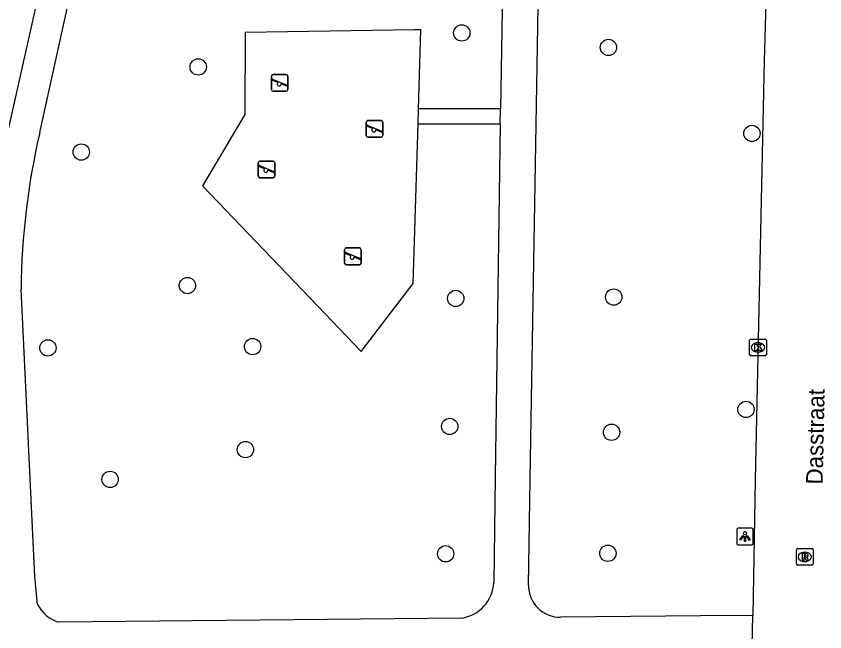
# Model space of a CAD drawing. Extents: x 160026 to 161302, y 384757 to 385701.
# Drawn here: x 160572.18 to 160620.67, y 385069.55 to 385106.46 of the extents above; entities that cross this region are included whole.
import ezdxf

# ---------------------------------------------------------------- set-up
doc = ezdxf.new("R2010")
doc.units = 0
for name, color, linetype in [('IMGEO_Boom', 7, 'Continuous'), ('IMGEO_Groenvoorziening', 7, 'Continuous'), ('IMGEO_Kolk', 7, 'Continuous'), ('IMGEO_Lichtpunt', 7, 'Continuous'), ('IMGEO_Openbare_ruimte_label', 7, 'Continuous'), ('IMGEO_Rijbaan_lokaal_open', 7, 'Continuous'), ('IMGEO_Rioolput', 7, 'Continuous'), ('IMGEO_Speelvoorziening', 7, 'Continuous'), ('IMGEO_Voetpad_halfverhard', 7, 'Continuous'), ('IMGEO_Voetpad_open', 7, 'Continuous')]:
    doc.layers.add(name, color=color, linetype=linetype)

msp = doc.modelspace()

# ---------------------------------------------------------------- linework, layer by layer
at = {"layer": 'IMGEO_Boom'}
for centre in [(160598.907, 385105.453), (160607.7, 385104.584), (160583.098, 385103.416), (160616.302, 385099.428), (160576.086, 385098.313), (160582.456, 385090.311), (160598.543, 385089.536), (160608.015, 385089.62), (160586.361, 385086.65), (160574.086, 385086.576), (160615.942, 385082.883), (160598.183, 385081.863), (160607.884, 385081.515), (160585.934, 385080.475), (160577.817, 385078.689), (160597.938, 385074.229), (160607.664, 385074.262)]:
    msp.add_circle(centre, 0.489, dxfattribs=at)
at = {"layer": 'IMGEO_Groenvoorziening'}
msp.add_lwpolyline([(160596.316, 385100.901), (160596.459, 385105.638), (160596.079, 385105.632), (160585.921, 385105.485), (160585.887, 385100.571), (160583.363, 385096.295), (160590.273, 385089.07), (160592.87, 385086.354), (160595.998, 385090.43), (160596.289, 385100.012)], dxfattribs=at)
at = {"layer": 'IMGEO_Kolk'}
for p, q in [((160616.241, 385087.103), (160617.093, 385087.103)), ((160616.166, 385086.177), (160616.166, 385087.029)), ((160616.654, 385086.883), (160616.679, 385086.883)), ((160617.167, 385087.029), (160617.167, 385086.177)), ((160616.677, 385086.323), (160616.652, 385086.323)), ((160617.093, 385086.103), (160616.241, 385086.103))]:
    msp.add_line(p, q, dxfattribs=at)
for points in [[(160616.241, 385087.103), (160617.093, 385087.103)], [(160616.166, 385086.177), (160616.166, 385087.029)], [(160616.487, 385086.803), (160616.61, 385086.803), (160616.61, 385086.652), (160616.74, 385086.803), (160616.904, 385086.803), (160616.758, 385086.652), (160616.911, 385086.403), (160616.759, 385086.403), (160616.674, 385086.567), (160616.61, 385086.5), (160616.61, 385086.403), (160616.487, 385086.403), (160616.487, 385086.803)], [(160617.167, 385087.029), (160617.167, 385086.177)], [(160617.093, 385086.103), (160616.241, 385086.103)]]:
    msp.add_lwpolyline(points, dxfattribs=at)
for centre, start, end in [((160616.243, 385087.027), 91.552, 178.448), ((160616.243, 385087.027), 91.552, 178.448), ((160617.091, 385087.027), 1.552, 88.448), ((160617.091, 385087.027), 1.552, 88.448), ((160616.243, 385086.179), 181.552, 268.448), ((160616.243, 385086.179), 181.552, 268.448), ((160617.091, 385086.179), 271.552, 358.448), ((160617.091, 385086.179), 271.552, 358.448)]:
    msp.add_arc(centre, 0.0765, start, end, dxfattribs=at)
for centre, major_axis, ratio, start_param, end_param in [((160616.653, 385086.603), (-0.387, 0.002), 0.722429, 4.712389, 7.853982), ((160616.678, 385086.603), (-0.39, 0.002), 0.717154, 1.570796, 4.712389)]:
    msp.add_ellipse(centre, major_axis=major_axis, ratio=ratio, start_param=start_param, end_param=end_param, dxfattribs=at)
at = {"layer": 'IMGEO_Lichtpunt'}
for p, q in [((160615.389, 385075.664), (160615.389, 385074.857)), ((160615.389, 385075.664), (160615.389, 385074.857)), ((160616.291, 385075.759), (160615.483, 385075.759)), ((160616.291, 385075.759), (160615.483, 385075.759)), ((160616.385, 385074.857), (160616.385, 385075.664)), ((160616.385, 385074.857), (160616.385, 385075.664)), ((160615.483, 385074.763), (160616.291, 385074.763)), ((160615.483, 385074.763), (160616.291, 385074.763))]:
    msp.add_line(p, q, dxfattribs=at)
for points in [[(160615.763, 385075.328), (160615.802, 385075.3), (160615.614, 385075.038), (160615.576, 385075.065), (160615.763, 385075.328)], [(160615.865, 385075.28), (160615.912, 385075.28), (160615.912, 385074.958), (160615.865, 385074.958), (160615.865, 385075.28)], [(160615.975, 385075.3), (160616.013, 385075.327), (160616.2, 385075.065), (160616.161, 385075.037), (160615.975, 385075.3)]]:
    msp.add_lwpolyline(points, dxfattribs=at)
msp.add_circle((160615.888, 385075.462), 0.0994, dxfattribs=at)
for centre, start, end in [((160615.483, 385075.664), 90, 180), ((160615.483, 385075.664), 90, 180), ((160616.291, 385075.664), 0, 90), ((160616.291, 385075.664), 0, 90), ((160615.483, 385074.857), 180, 270), ((160615.483, 385074.857), 180, 270), ((160616.291, 385074.857), 270, 0), ((160616.291, 385074.857), 270, 360)]:
    msp.add_arc(centre, 0.0946, start, end, dxfattribs=at)
at = {"layer": 'IMGEO_Rijbaan_lokaal_open'}
for points in [[(160617.43, 385117.621), (160617.044, 385103.79), (160616.494, 385078.673), (160616.352, 385070.534)], [(160616.32, 385068.707), (160616.352, 385070.534)]]:
    msp.add_lwpolyline(points, dxfattribs=at)
at = {"layer": 'IMGEO_Rioolput'}
for p, q in [((160619.048, 385074.546), (160619.9, 385074.546)), ((160618.973, 385073.62), (160618.973, 385074.472)), ((160619.461, 385074.326), (160619.486, 385074.326)), ((160619.974, 385074.472), (160619.974, 385073.62)), ((160619.9, 385073.546), (160619.048, 385073.546)), ((160619.484, 385073.766), (160619.459, 385073.766))]:
    msp.add_line(p, q, dxfattribs=at)
for points in [[(160619.048, 385074.546), (160619.9, 385074.546)], [(160618.973, 385073.62), (160618.973, 385074.472)], [(160619.562, 385074.244), (160619.31, 385074.246), (160619.31, 385073.846)], [(160619.31, 385073.846), (160619.434, 385073.846), (160619.434, 385074.008), (160619.445, 385074.008)], [(160619.488, 385074.165), (160619.434, 385074.165), (160619.434, 385074.084)], [(160619.434, 385074.084), (160619.486, 385074.084)], [(160619.974, 385074.472), (160619.974, 385073.62)], [(160619.9, 385073.546), (160619.048, 385073.546)], [(160619.492, 385073.979), (160619.563, 385073.846), (160619.703, 385073.846), (160619.638, 385073.972)]]:
    msp.add_lwpolyline(points, dxfattribs=at)
for centre, radius, start, end in [((160619.05, 385074.47), 0.0765, 91.552, 178.448), ((160619.05, 385074.47), 0.0765, 91.552, 178.448), ((160619.898, 385074.47), 0.0765, 1.552, 88.448), ((160619.898, 385074.47), 0.0765, 1.552, 88.448), ((160619.444, 385073.955), 0.0533, 26.0293, 88.6989), ((160619.47, 385074.273), 0.19, 274.7715, 282.9687), ((160619.494, 385074.069), 0.0964, 77.0061, 93.1865), ((160619.508, 385074.126), 0.0378, 276.6634, 79.6772), ((160619.561, 385074.134), 0.109, 350.3612, 89.416), ((160619.559, 385074.134), 0.112, 277.5842, 350.9817), ((160619.543, 385073.919), 0.108, 29.5134, 73.7905), ((160619.05, 385073.622), 0.0765, 181.552, 268.448), ((160619.05, 385073.622), 0.0765, 181.552, 268.448), ((160619.898, 385073.622), 0.0765, 271.552, 358.448), ((160619.898, 385073.622), 0.0765, 271.552, 358.448)]:
    msp.add_arc(centre, radius, start, end, dxfattribs=at)
for centre, major_axis, ratio, start_param, end_param in [((160619.46, 385074.046), (-0.387, 0.002), 0.722429, 4.712389, 7.853982), ((160619.485, 385074.046), (-0.39, 0.002), 0.717154, 1.570796, 4.712389)]:
    msp.add_ellipse(centre, major_axis=major_axis, ratio=ratio, start_param=start_param, end_param=end_param, dxfattribs=at)
at = {"layer": 'IMGEO_Speelvoorziening'}
for p, q in [((160587.494, 385102.054), (160587.494, 385102.854)), ((160587.494, 385102.854), (160587.494, 385102.054)), ((160587.877, 385102.482), (160587.538, 385102.619)), ((160587.563, 385102.679), (160588.439, 385102.326)), ((160587.594, 385102.954), (160588.384, 385102.954)), ((160588.384, 385102.954), (160587.594, 385102.954)), ((160588.484, 385102.854), (160588.484, 385102.054)), ((160588.484, 385102.054), (160588.484, 385102.854)), ((160588.415, 385102.266), (160588.075, 385102.403)), ((160588.384, 385101.954), (160587.594, 385101.954)), ((160587.594, 385101.954), (160588.384, 385101.954)), ((160593.272, 385100.198), (160594.062, 385100.198)), ((160594.062, 385100.198), (160593.272, 385100.198)), ((160593.172, 385099.298), (160593.172, 385100.098)), ((160593.172, 385100.098), (160593.172, 385099.298)), ((160593.555, 385099.726), (160593.216, 385099.863)), ((160593.241, 385099.923), (160594.117, 385099.57)), ((160594.162, 385100.098), (160594.162, 385099.298)), ((160594.162, 385099.298), (160594.162, 385100.098)), ((160594.093, 385099.51), (160593.753, 385099.647)), ((160594.062, 385099.198), (160593.272, 385099.198)), ((160593.272, 385099.198), (160594.062, 385099.198)), ((160586.798, 385097.774), (160587.588, 385097.774)), ((160587.588, 385097.774), (160586.798, 385097.774)), ((160586.698, 385096.874), (160586.698, 385097.674)), ((160586.698, 385097.674), (160586.698, 385096.874)), ((160587.081, 385097.302), (160586.742, 385097.439)), ((160586.767, 385097.499), (160587.643, 385097.146)), ((160587.688, 385097.674), (160587.688, 385096.874)), ((160587.688, 385096.874), (160587.688, 385097.674)), ((160587.619, 385097.086), (160587.279, 385097.223)), ((160587.588, 385096.774), (160586.798, 385096.774)), ((160586.798, 385096.774), (160587.588, 385096.774)), ((160591.877, 385091.662), (160591.877, 385092.462)), ((160591.877, 385092.462), (160591.877, 385091.662)), ((160591.977, 385092.562), (160592.767, 385092.562)), ((160592.767, 385092.562), (160591.977, 385092.562)), ((160592.867, 385092.462), (160592.867, 385091.662)), ((160592.867, 385091.662), (160592.867, 385092.462)), ((160592.26, 385092.09), (160591.921, 385092.227)), ((160591.946, 385092.287), (160592.822, 385091.934)), ((160592.798, 385091.874), (160592.458, 385092.011)), ((160592.767, 385091.562), (160591.977, 385091.562)), ((160591.977, 385091.562), (160592.767, 385091.562))]:
    msp.add_line(p, q, dxfattribs=at)
for centre, radius, start, end in [((160587.594, 385102.854), 0.1, 90, 180), ((160587.594, 385102.854), 0.1, 90, 180), ((160587.551, 385102.649), 0.0327, 68.078, 248.078), ((160588.384, 385102.854), 0.1, 0, 90), ((160588.384, 385102.854), 0.1, 360, 90), ((160587.956, 385102.392), 0.12, 130.9928, 5.1632), ((160588.427, 385102.296), 0.0327, 248.078, 68.078), ((160587.594, 385102.054), 0.1, 180, 270), ((160587.594, 385102.054), 0.1, 180, 270), ((160588.384, 385102.054), 0.1, 270, 0), ((160588.384, 385102.054), 0.1, 270, 0), ((160593.272, 385100.098), 0.1, 90, 180), ((160593.272, 385100.098), 0.1, 90, 180), ((160594.062, 385100.098), 0.1, 0, 90), ((160594.062, 385100.098), 0.1, 360, 90), ((160593.229, 385099.893), 0.0327, 68.078, 248.078), ((160593.634, 385099.636), 0.12, 130.9928, 5.1632), ((160593.272, 385099.298), 0.1, 180, 270), ((160593.272, 385099.298), 0.1, 180, 270), ((160594.062, 385099.298), 0.1, 270, 0), ((160594.062, 385099.298), 0.1, 270, 0), ((160594.105, 385099.54), 0.0327, 248.078, 68.078), ((160586.798, 385097.674), 0.1, 90, 180), ((160586.798, 385097.674), 0.1, 90, 180), ((160587.588, 385097.674), 0.1, 0, 90), ((160587.588, 385097.674), 0.1, 360, 90), ((160586.755, 385097.469), 0.0327, 68.078, 248.078), ((160587.16, 385097.212), 0.12, 130.9928, 5.1632), ((160586.798, 385096.874), 0.1, 180, 270), ((160586.798, 385096.874), 0.1, 180, 270), ((160587.588, 385096.874), 0.1, 270, 0), ((160587.588, 385096.874), 0.1, 270, 0), ((160587.631, 385097.116), 0.0327, 248.078, 68.078), ((160591.977, 385092.462), 0.1, 90, 180), ((160591.977, 385092.462), 0.1, 90, 180), ((160592.767, 385092.462), 0.1, 0, 90), ((160592.767, 385092.462), 0.1, 360, 90), ((160591.934, 385092.257), 0.0327, 68.078, 248.078), ((160592.339, 385092), 0.12, 130.9928, 5.1632), ((160591.977, 385091.662), 0.1, 180, 270), ((160591.977, 385091.662), 0.1, 180, 270), ((160592.767, 385091.662), 0.1, 270, 0), ((160592.767, 385091.662), 0.1, 270, 0), ((160592.81, 385091.904), 0.0327, 248.078, 68.078)]:
    msp.add_arc(centre, radius, start, end, dxfattribs=at)
at = {"layer": 'IMGEO_Voetpad_halfverhard'}
for points in [[(160571.746, 385099.761), (160579.038, 385132.279), (160578.019, 385132.528), (160574.748, 385133.329)], [(160573.602, 385099.491), (160580.73, 385131.864), (160601.673, 385126.736), (160601.584, 385121.69), (160601.571, 385120.941), (160601.218, 385100.91)], [(160602.909, 385072.356), (160603.035, 385079.917), (160603.449, 385104.674), (160603.489, 385107.085), (160605.504, 385107.037), (160605.686, 385117.9), (160614.133, 385117.699), (160617.43, 385117.621)], [(160601.202, 385099.997), (160600.915, 385078.818), (160600.828, 385072.508)], [(160573.469, 385071.185), (160573.31, 385072.874), (160572.478, 385090.094)], [(160598.883, 385070.368), (160574.712, 385070.141)], [(160616.352, 385070.534), (160613.21, 385070.504), (160604.827, 385070.424)]]:
    msp.add_lwpolyline(points, dxfattribs=at)
for centre, radius, start, end in [((160615.655, 385089.695), 43.179, 166.8874, 179.4708), ((160598.54, 385072.633), 2.291, 278.6044, 356.8616), ((160604.809, 385072.324), 1.901, 179.05, 270.5333), ((160575.325, 385072.133), 2.084, 207.0531, 252.8929)]:
    msp.add_arc(centre, radius, start, end, dxfattribs=at)
at = {"layer": 'IMGEO_Voetpad_open'}
for points in [[(160596.289, 385100.012), (160596.316, 385100.901)], [(160601.218, 385100.91), (160596.316, 385100.901)], [(160601.202, 385099.997), (160601.218, 385100.91)], [(160596.289, 385100.012), (160601.202, 385099.997)]]:
    msp.add_lwpolyline(points, dxfattribs=at)

# ---------------------------------------------------------------- texts
at = {"layer": 'IMGEO_Openbare_ruimte_label'}
msp.add_text('Dasstraat', height=1, rotation=88.797, dxfattribs=at).set_placement((160620.544, 385078.377))

doc.saveas('drawing.dxf')
